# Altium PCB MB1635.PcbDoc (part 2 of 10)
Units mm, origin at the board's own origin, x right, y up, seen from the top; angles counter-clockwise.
Board outline 127 x 97 mm, 6 copper layers (Top Layer, Signal Layer 1, Signal Layer 2, Signal Layer 3, Signal Layer 4, Bottom Layer), stack 1.557 mm thick; 593 components, 478 nets, 2435 pads, 1743 vias.
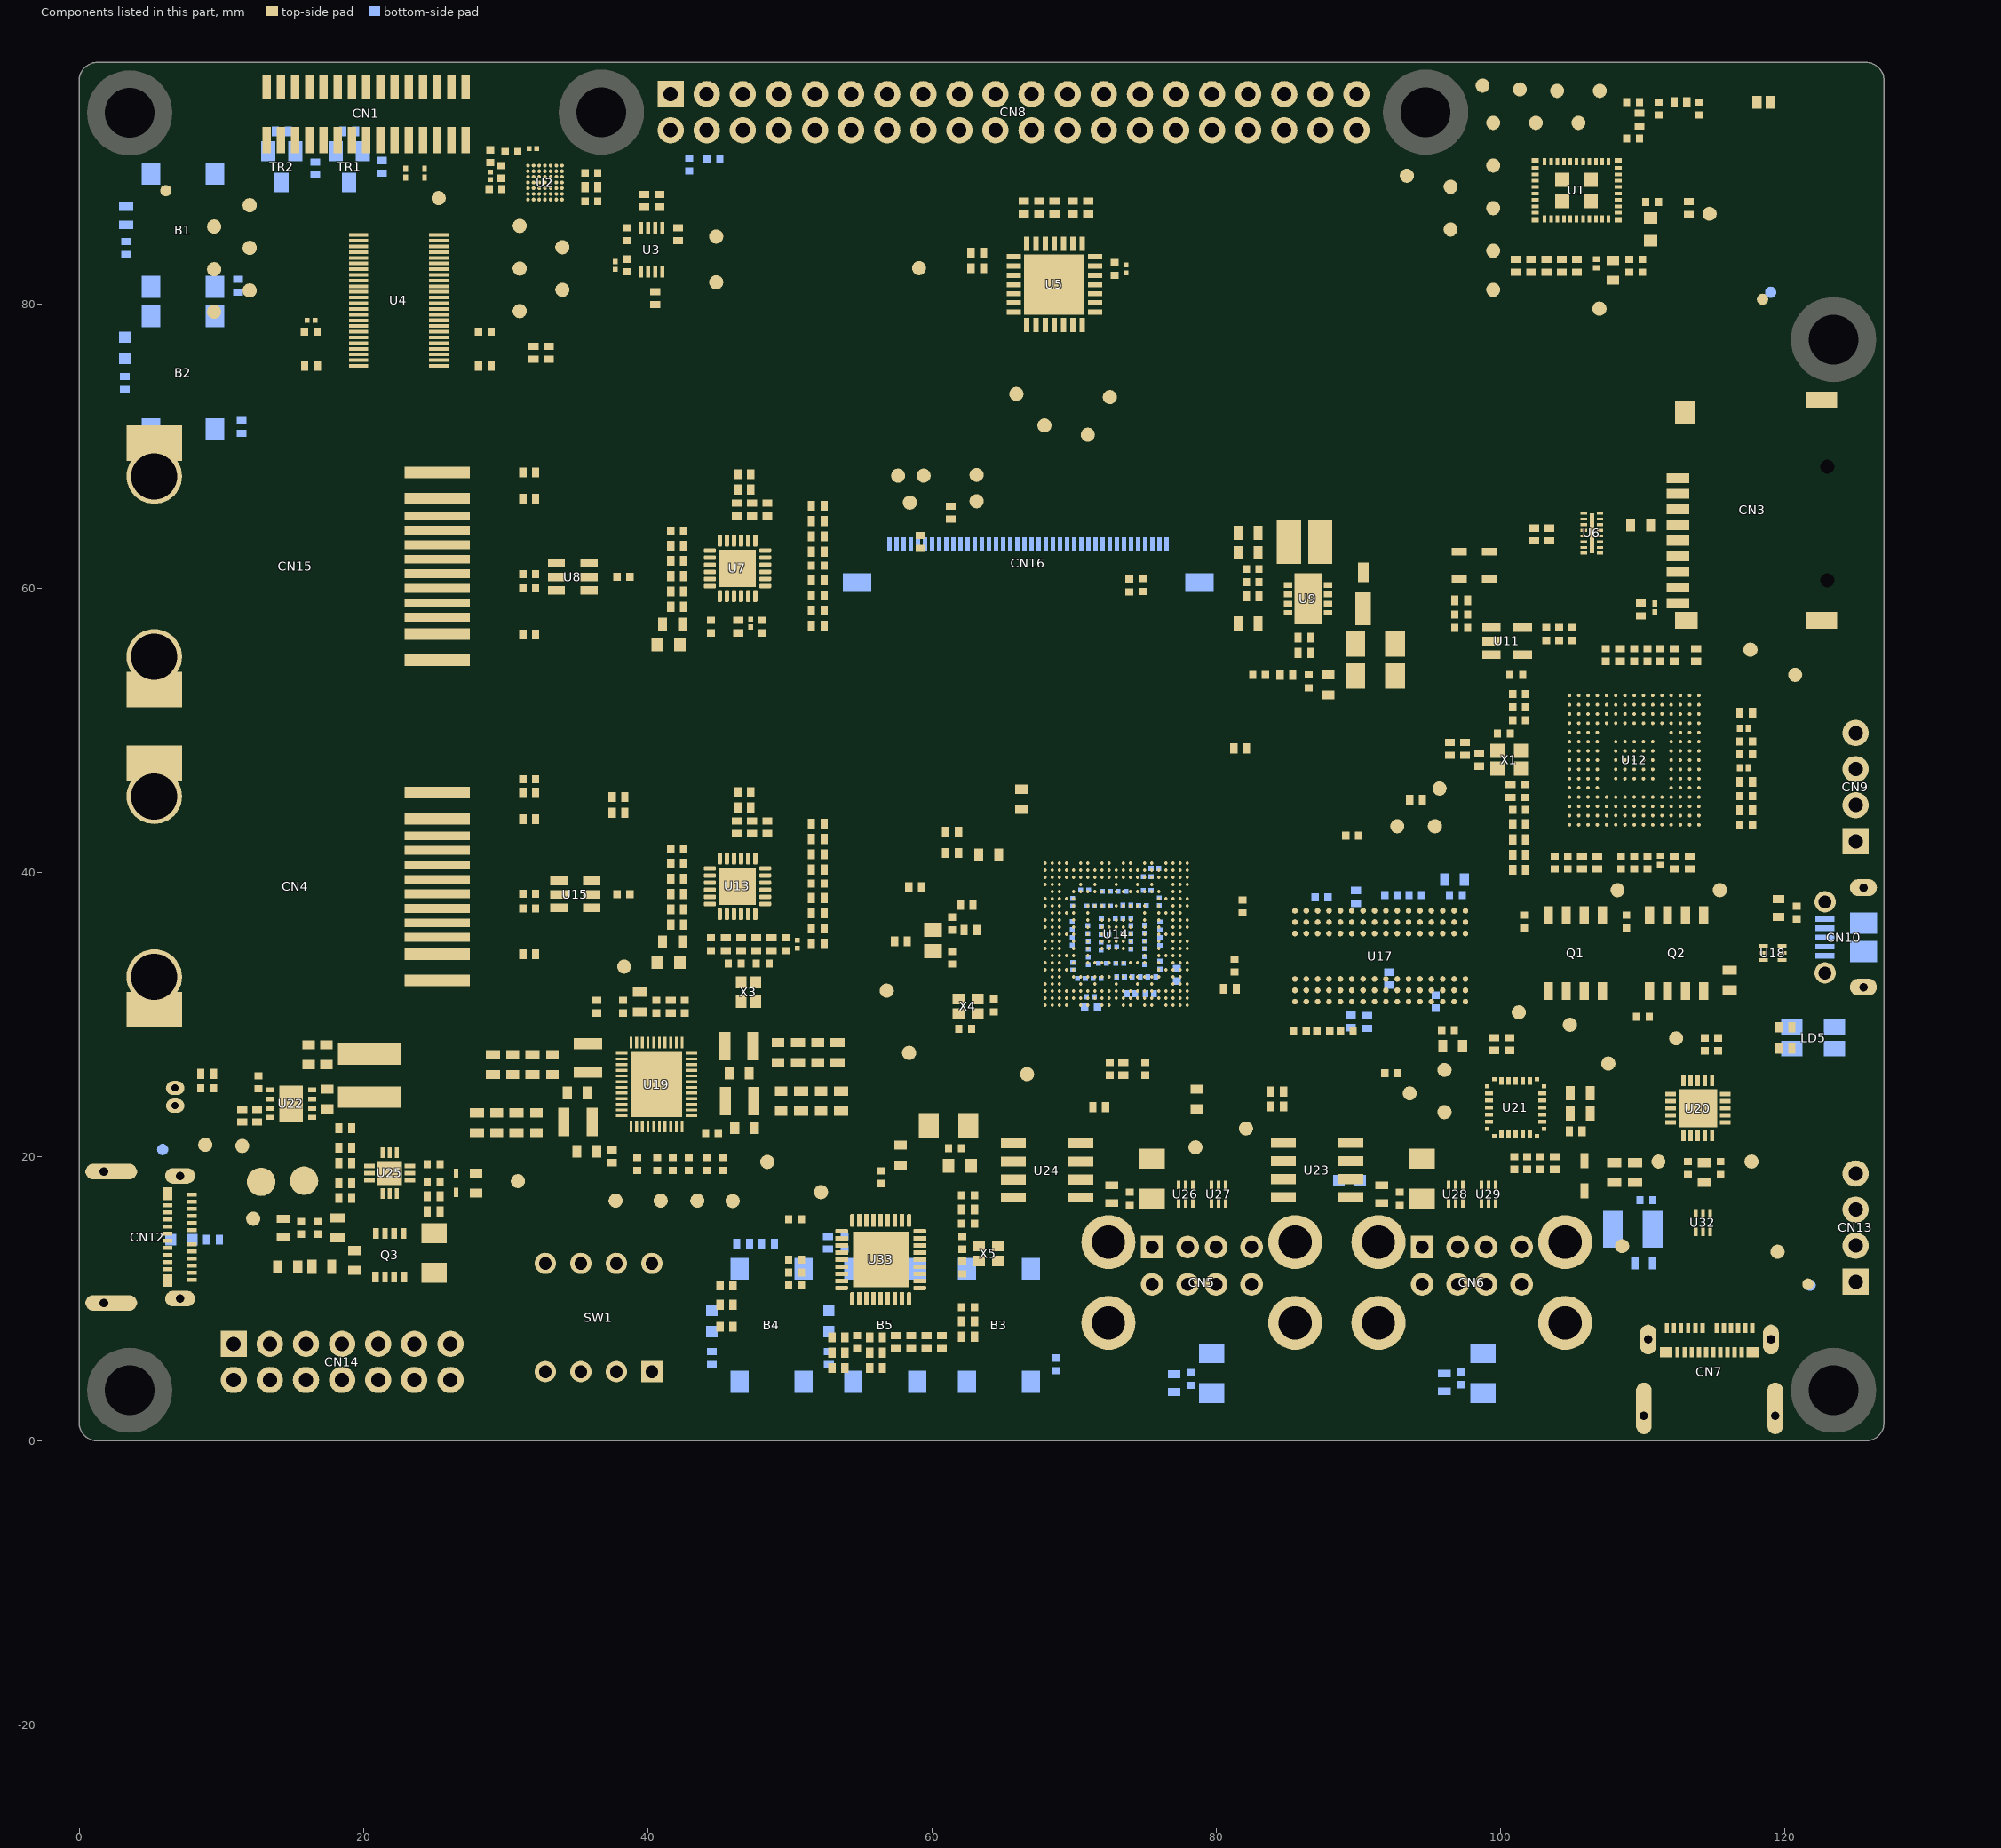
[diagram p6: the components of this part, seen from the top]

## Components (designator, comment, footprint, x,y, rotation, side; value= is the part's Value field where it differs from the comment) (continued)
U12 "ST-LINKV3E" ICC_UFBGA201_176+25_10X10_P065 109.425,47.9 r0 top value=ST-LINKV3S
U13 "LAN8742A-CZ-TR" ICC_VQFN24-EPAD_4X4_P050 46.325,39.025 r90 top
U14 "STM32MP135FAF7" ICC_TFBGA320_11X11_STM32MP135FA7_P050_H1P20 72.975,35.65 r0 top locked
U15 "USBLC6-4SC6" ESD_SOT23-6L 34.9,38.45 r270 top
U16 "ESD-TRANSIL" ESD_QFN2_1P6X1_P125 119.575,37.5 r90 top value=ESDA7P60-1U1M
U17 "NT5CC256M16ER-EK" ICC_VFBGA96_9x13_P080 91.55,34.1 r270 top locked
U18 "ECMF02-2AMX6" ESD_QFN-6L_1P7X1P5_P050 119.175,34.325 r270 top
U19 "STPMU1" ICC_WFQFN44-EPAD_5X6_P040 40.625,25.075 r0 top value=STPMIC1DPQR
U20 "TCPP03-M20" ICC_QFN20-EPAD_4X4_P050 113.9,23.4 r270 top
U21 "STM32G071G8U6N" ICC_UFQFPN28_4X4_P050 101.075,23.45 r0 top
U22 "ST1S31PUR" ICC_VFDFPN8-EPAD_3X3_P065 14.925,23.725 r270 top
U23 "STMPS2252MTR" ICC_SO8_5X4_P127 87.1,19.05 r270 top
U24 "STMPS2252MTR" ICC_SO8_5X4_P127 68.1,19.025 r270 top
U25 "TCPP01-M12" ICC_QFN12L-EPAD_3X3_P050 21.845,18.839 r270 top
U26 "ECMF02-2AMX6" ESD_QFN-6L_1P7X1P5_P050 77.85,17.35 r180 top
U27 "ECMF02-2AMX6" ESD_QFN-6L_1P7X1P5_P050 80.175,17.35 r180 top
U28 "ECMF02-2AMX6" ESD_QFN-6L_1P7X1P5_P050 96.85,17.35 r180 top
U29 "ECMF02-2AMX6" ESD_QFN-6L_1P7X1P5_P050 99.175,17.35 r180 top
U30 "ESD-TRANSIL" ESD_QFN1610_2N_1K_2A 72.65,17.35 r90 top value=ESDA7P120-1U1M
U31 "ESD-TRANSIL" ESD_QFN1610_2N_1K_2A 91.65,17.35 r90 top value=ESDA7P120-1U1M
U32 "ECMF02-2AMX6" ESD_QFN-6L_1P7X1P5_P050 114.25,15.35 r180 top
U33 "USB2514B-AEZC" ICC_QFN36-EPAD_6X6_P050 56.4,12.75 r180 top
U34 "ESD-TRANSIL" ESD_QFN1610_2N_1K_2A 14.345,14.989 r270 top value=ESDA25P35-1U1M
U35 "RK043FN78H-CT661C" LCD_DRAWING_ROCKTEK_RK043FN78H-CT661C 66.775,64.836 r180 bottom
U36 "ESD-TRANSIL" ESD_QFN1610_2N_1K_2A 110.1,12.523 r180 bottom value=ESDA25P35-1U1M
U37 "ESD-TRANSIL" ESD_ST0201 54.692,13.937 r90 bottom value=ESDALC6V1-1U2
U38 "ESD-TRANSIL" ESD_QFN1610_2N_1K_2A 96.075,4.1 r270 bottom value=ESDA7P120-1U1M
U39 "ESD-TRANSIL" ESD_QFN1610_2N_1K_2A 77.05,4.05 r270 bottom value=ESDA7P120-1U1M
U40 "ESD-TRANSIL" ESD_ST0201 24.3,89.213 r270 top value=ESDALC6V1-1U2
U41 "ESD-TRANSIL" ESD_ST0201 22.975,89.2 r270 top value=ESDALC6V1-1U2
X1 "OSCILLATOR_4_PINS" OSC_NDK_NZ2520SB_4P 100.625,47.925 r0 top value=25MHz
X2 "XTAL_2_PINS" CRY_NX2012SA_2P 60.075,35.2 r270 top value=32.768KHz
X3 "XTAL_4_PINS" CRY_NX2016SA_4P 47.1,31.575 r90 top value=25MHz
X4 "XTAL_4_PINS" CRY_NX2016SA_4P 62.55,30.575 r0 top value=24MHz
X5 "XTAL_4_PINS" CRY_NX2016SA_4P 63.975,13.175 r180 top value=24MHz

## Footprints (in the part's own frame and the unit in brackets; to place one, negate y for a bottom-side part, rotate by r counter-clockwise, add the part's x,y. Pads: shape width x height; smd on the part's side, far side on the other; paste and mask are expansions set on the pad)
C0201_H0P5 [mm] "MCD-01534"
  rect 0.4x0.5 smd mask+0.05: 1(-0.3,0) 2(0.3,0)
  Top Layer keep-out region: -0.099,-0.25 0.101,-0.25 0.101,0.25 -0.099,0.25
  body extent -0.35,-0.2 0.35,0.2, height 0.55
C0201_MURATA_GRM033_H0P3 [mm] "GRM033R60J105ME11"
  rect 0.35x0.35 smd mask+0.05: 1(-0.275,0) 2(0.275,0)
  Top Layer keep-out region: -0.1,-0.175 0.1,-0.175 0.1,0.175 -0.1,0.175
  body extent -0.32,-0.17 0.32,0.17, height 0.33
C0402#1 [mm]
  rect 0.51x0.56 smd mask+0.05: 1(-0.45,0) 2(0.45,0)
  Top Layer keep-out region: -0.175,-0.275 0.175,-0.275 0.175,0.275 -0.175,0.275
  body extent -0.5,-0.3 0.5,0.3, height 0.4
C0402#2 [mm]
  rect 0.51x0.56 smd mask+0.05: 1(-0.45,0) 2(0.45,0)
  body extent -0.5,-0.3 0.5,0.3, height 0.4
C0603 [mm]
  rect 0.64x0.89 smd mask+0.05: 1(-0.7,0) 2(0.7,0)
  Top Layer keep-out region: -0.375,-0.45 0.375,-0.45 0.375,0.45 -0.375,0.45
  body extent -0.9,-0.5 0.9,0.5, height 1.4
C0603_H0P8 [mm] "MCD-01540"
  rect 0.64x0.89 smd mask+0.05: 1(-0.7,0) 2(0.7,0)
  body extent -0.9,-0.5 0.9,0.5, height 1
C1206_H1P6 [mm]
  rect 1.4x1.78 smd mask+0.05: 1(-1.4,0) 2(1.4,0)
  silkscreen extent -2.12,-0.97 2.15,0.97, body extent -1.7,-0.9 1.7,0.9, height 1.8
C1206_H1P25 [mm]
  rect 1.4x1.78 smd mask+0.05: 1(-1.4,0) 2(1.4,0)
  silkscreen extent -2.12,-0.97 2.15,0.97, body extent -1.7,-0.9 1.7,0.9, height 1.45
C1210 [mm]
  rect 1.4x2.6 smd mask+0.05: 1(-1.4,0) 2(1.4,0)
  silkscreen extent -2.1,-1.43 2.1,1.43, body extent -1.75,-1.35 1.75,1.35, height 2.5
CON_DUAL-USB-TYPE-A_CONEXCON_5600-3081 [mm]
  round 1.6 hole 0.92: B1(-3.5,13.01) B2(-1,13.01) B3(1,13.01) B4(3.5,13.01) T2(-1,15.63) T3(1,15.63) T4(3.5,15.63)
  round 3.8 hole 2.33: CH1(6.57,10.3) CH2(-6.57,10.3) CH3(-6.57,15.98) CH4(6.57,15.98)
  rect 1.6x1.6 hole 0.92: T1(-3.5,15.63)
  silkscreen extent -7.3,-0.4 7.3,17.85, body extent -7.83,-0.6 7.87,17.85, height 16.2
CON_MICROSD_ATOM_MR01A-01211 [mm]
  rect 0.7x1.6 smd paste+0 mask+0.05: 1(2.25,14.5) 2(1.15,14.5) 3(0.05,14.5) 4(-1.05,14.5) 5(-2.15,14.5) 6(-3.25,14.5) 7(-4.35,14.5) 8(-5.45,14.5) 9(-6.55,14.5)
  rect 1.2x1.6 smd paste+0 mask+0.05: 10(-7.75,13.9)
  rect 1.2x2.2 smd paste+0 mask+0.05: 11(-7.75,4.4) 12(7.75,4.4)
  rect 1.6x1.4 smd paste+0 mask+0.05: 13(6.85,14)
  round 0.5 hole 1 unplated paste-10 mask+0.05: NPTH1(-4.95,4) NPTH2(3.05,4)
  Top Layer pour cut-out: -8.35,8.1 -8.35,12.9 -6.9,12.9 -6.9,8.1
  Top Layer pour cut-out: -6.1,10.1 2.9,10.1 2.9,8.1 -6.1,8.1
  Top Layer keep-out region: -8.35,8.1 -8.35,12.9 -6.9,12.9 -6.9,8.1
  Top Layer keep-out region: -6.1,10.1 2.9,10.1 2.9,8.1 -6.1,8.1
  silkscreen extent -7.35,-5.3 7.35,14.5, body extent -8.05,0 8.05,15, height 1.9
CON_MOLEX_53047-0210 [mm]
  oval 1x1.3 hole 0.5 mask+0.05: 1(-0.625,0) 2(0.625,0)
  silkscreen extent -2.12,-1.15 2.13,2.05, body extent -2.12,-1.15 2.13,2.05, height 4.2
CON_MOLEX_5051104091 [mm] "MCD-02589"
  rect 0.3x1 smd mask+0.05: 1(-9.75,1.1) 2(-9.25,1.1) 3(-8.75,1.1) 4(-8.25,1.1) 5(-7.75,1.1) 6(-7.25,1.1) 7(-6.75,1.1) 8(-6.25,1.1) 9(-5.75,1.1) 10(-5.25,1.1) 11(-4.75,1.1) 12(-4.25,1.1) 13(-3.75,1.1) 14(-3.25,1.1) 15(-2.75,1.1) 16(-2.25,1.1) 17(-1.75,1.1) 18(-1.25,1.1) 19(-0.75,1.1) 20(-0.25,1.1) 21(0.25,1.1) 22(0.75,1.1) 23(1.25,1.1) 24(1.75,1.1) 25(2.25,1.1) 26(2.75,1.1) 27(3.25,1.1) 28(3.75,1.1) 29(4.25,1.1) 30(4.75,1.1) 31(5.25,1.1) 32(5.75,1.1) 33(6.25,1.1) 34(6.75,1.1) 35(7.25,1.1) 36(7.75,1.1) 37(8.25,1.1) 38(8.75,1.1) 39(9.25,1.1) 40(9.75,1.1)
  rect 2x1.3 smd mask+0.05: MT1(-12.05,-1.6) MT2(12.05,-1.6)
  silkscreen extent -12.35,-4 12.35,1.25, body extent -12.75,-4 12.75,1.3, height 1.88
CON_RJ45_PHC_RMT-119A-12F6-GY-02 [mm] "MCD-02475"
  rect 0.81x4.6 smd mask+0.05: 1(6.61,25.2) 2(4.77,25.2) 11(-4.77,25.2) 12(-6.61,25.2)
  rect 0.61x4.6 smd mask+0.05: 3(3.57,25.2) 4(2.55,25.2) 5(1.53,25.2) 6(0.51,25.2) 7(-0.51,25.2) 8(-1.53,25.2) 9(-2.55,25.2) 10(-3.57,25.2)
  rect 2.5x3.9 smd mask+0.05: 13(-8.67,5.28) 14(8.67,5.28)
  round 3.9 hole 3.25 mask+0.05: 13(-6.35,5.28) 14(6.35,5.28)
  silkscreen extent -8.9,-0.01 8.9,25.65, body extent -9.5,0 9.5,25.65, height 13.61
CON_SAMTEC_TSW-104-07-G-S [mm]
  rect 1.85x1.85 / inner round 1.85 / far side rect 1.85x1.85 hole 1 mask+0.05: 1(-3.81,0)
  round 1.85 hole 1 mask+0.05: 2(-1.27,0) 3(1.27,0) 4(3.81,0)
  silkscreen extent -5.12,-1.3 5.12,1.3, body extent -5.21,-1.37 5.18,1.37, height 8.38
CON_SAMTEC_TSW-107-07-X-D [mm] "MCD-02123"
  rect 1.85x1.85 / inner round 1.85 / far side rect 1.85x1.85 hole 1 mask+0.05: 1(-7.62,-1.27)
  round 1.85 hole 1 mask+0.05: 2(-7.62,1.27) 3(-5.08,-1.27) 4(-5.08,1.27) 5(-2.54,-1.27) 6(-2.54,1.27) 7(0,-1.27) 8(0,1.27) 9(2.54,-1.27) 10(2.54,1.27) 11(5.08,-1.27) 12(5.08,1.27) 13(7.62,-1.27) 14(7.62,1.27)
  silkscreen extent -8.89,-2.54 8.89,2.54, body extent -8.89,-2.55 8.89,2.54, height 8.38
CON_SAMTEC_TSW-120-07-G-D [mm]
  rect 1.85x1.85 / inner round 1.85 / far side rect 1.85x1.85 hole 1 mask+0.05: 1(-24.13,-1.27)
  round 1.85 hole 1 mask+0.05: 2(-24.13,1.27) 3(-21.59,-1.27) 4(-21.59,1.27) 5(-19.05,-1.27) 6(-19.05,1.27) 7(-16.51,-1.27) 8(-16.51,1.27) 9(-13.97,-1.27) 10(-13.97,1.27) 11(-11.43,-1.27) 12(-11.43,1.27) 13(-8.89,-1.27) 14(-8.89,1.27) 15(-6.35,-1.27) 16(-6.35,1.27) 17(-3.81,-1.27) 18(-3.81,1.27) 19(-1.27,-1.27) 20(-1.27,1.27) 21(1.27,-1.27) 22(1.27,1.27) 23(3.81,-1.27) 24(3.81,1.27) 25(6.35,-1.27) 26(6.35,1.27) 27(8.89,-1.27) 28(8.89,1.27) 29(11.43,-1.27) 30(11.43,1.27) 31(13.97,-1.27) 32(13.97,1.27) 33(16.51,-1.27) 34(16.51,1.27) 35(19.05,-1.27) 36(19.05,1.27) 37(21.59,-1.27) 38(21.59,1.27) 39(24.13,-1.27) 40(24.13,1.27)
  silkscreen extent -25.4,-2.54 25.4,2.54, body extent -25.4,-2.55 25.4,2.54, height 8.38
CON_TE-CONNECTIVITY_1-1734248-5 [mm] "MCD-02225"
  rect 0.6x1.85 smd mask+0.05: 1(7,1.875) 2(6,1.875) 3(5,1.875) 4(4,1.875) 5(3,1.875) 6(2,1.875) 7(1,1.875) 8(0,1.875) 9(-1,1.875) 10(-2,1.875) 11(-3,1.875) 12(-4,1.875) 13(-5,1.875) 14(-6,1.875) 15(-7,1.875)
  rect 0.6x1.65 smd mask+0.05: 16(7,-1.875) 17(6,-1.875) 18(5,-1.875) 19(4,-1.875) 20(3,-1.875) 21(2,-1.875) 22(1,-1.875) 23(0,-1.875) 24(-1,-1.875) 25(-2,-1.875) 26(-3,-1.875) 27(-4,-1.875) 28(-5,-1.875) 29(-6,-1.875) 30(-7,-1.875)
  silkscreen extent -11.2,-2.85 11.2,1.85, body extent -11.2,-2.7 11.2,2.4, height 7.7
CON_USB-TYPEC_MOLEX_2012670005 [mm] "MCD-02421"
  rect 0.3x0.7 smd mask+0.05: A1(-3,3.085) A2(-2.5,3.085) A3(-2,3.085) A4(-1.5,3.085) A5(-1,3.085) A6(-0.5,3.085) A7(0.5,3.085) A8(1,3.085) A9(1.5,3.085) A10(2,3.085) A11(2.5,3.085) A12(3,3.085) B2(2.25,1.385) B3(1.75,1.385) B4(1.25,1.385) B5(0.75,1.385) B6(0.25,1.385) B7(-0.25,1.385) B8(-0.75,1.385) B9(-1.25,1.385) B10(-1.75,1.385) B11(-2.25,1.385)
  rect 0.9x0.7 smd mask+0.05: B1(3.05,1.385) B12(-3.05,1.385)
  oval 1.1x2.1 hole 0.6 slot 1.6 at 90 deg mask+0.05: SH1(-4.32,2.275) SH2(4.32,2.275)
  oval 1.1x2.6 hole 0.6 slot 2.1 at 90 deg mask+0.05: SH3(-4.62,-3.085) SH4(4.62,-3.085)
  oval 1.1x3.6 all layers, no hole mask+0.05: SH3(-4.62,-2.55) SH4(4.62,-2.55)
  silkscreen extent -4.7,-5.02 4.7,1.1, body extent -4.7,-5.03 4.69,3.27, height 3.67
CON_USBMICROB_MOLEX_105017-0001_H2P90 [mm]
  rect 0.4x1.35 smd mask+0.05: 1(-1.3,4.15) 2(-0.65,4.15) 3(0,4.15) 4(0.65,4.15) 5(1.3,4.15)
  round 1.5 hole 0.9 mask+0.05: 6(-2.5,4.15) 7(2.5,4.15)
  oval 1.2x1.9 hole 0.6 slot 1.3 at 90 deg mask+0.05: 8(3.5,1.45) 9(-3.5,1.45)
  rect 1.5x1.9 smd mask+0.05: 10(-1,1.45) 11(1,1.45)
  Top Layer region: 2.3,2.4 3.5,2.4 3.5,0.5 2.3,0.5 2.3,2.4
  Top Layer region: -3.5,2.4 -2.3,2.4 -2.3,0.5 -3.5,0.5 -3.5,2.4
  silkscreen extent -4,-0.7 4,4.6, body extent -4.1,-1.15 4.1,4.66, height 2.9
CRY_NX2012SA_2P [mm]
  rect 1x1.25 smd mask+0.05: 1(-0.75,0) 2(0.75,0)
  silkscreen extent -1.05,-0.75 1.05,0.75, body extent -1.05,-0.63 1.05,0.63, height 0.6
CRY_NX2016SA_4P [mm]
  rect 0.85x0.75 smd mask+0.05: 1(-0.675,-0.525) 2(0.675,-0.525) 3(0.675,0.525) 4(-0.675,0.525)
  silkscreen extent -1.22,-1.02 1.05,0.85, body extent -1.05,-0.85 1.05,0.85, height 0.7
DIO_DO216-AA [mm]
  rect 1.38x0.75 smd mask+0.05: 1(1.515,0)
  rect 2.32x1.1 smd mask+0.05: 2(-1.045,0)
  Top Layer region: -1.705,-1.015 0.115,-1.015 0.115,1.015 -1.705,1.015
  silkscreen extent -2.25,-1.22 0.72,1.22, body extent -2.02,-1.02 1.83,1.02, height 1.15
DIO_SOD323 [mm]
  rect 1.06x0.54 smd mask+0.05: 1(-1.07,0) 2(1.07,0)
  silkscreen extent -0.9,-0.72 0.9,0.72, body extent -1.3,-0.78 1.3,0.78, height 1.17
DIO_SOD523_1A_2K [mm] "MCD-01677"
  rect 0.65x0.3 smd mask+0.05: 1(-0.675,0) 2(0.675,0)
  silkscreen extent -0.65,-0.45 1.05,0.55, body extent -0.85,-0.45 0.85,0.45, height 0.71
ESD_QFN2_1P6X1_P125 [mm]
  rect 0.55x0.8 smd mask+0.05: 1(-0.625,0) 2(0.625,0)
  silkscreen extent -1,-0.55 0.85,0.55, body extent -0.85,-0.55 0.85,0.55, height 0.61
ESD_QFN1610_2N_1K_2A [mm] "DFN, 2-Leads, Body 1.60x1.00mm"
  rect 0.55x0.9 smd mask+0.05: 1(-0.625,0) 2(0.625,0)
  silkscreen extent -1.02,-0.58 0.85,0.58, body extent -0.85,-0.55 0.85,0.55, height 0.6
ESD_QFN-6L_1P7X1P5_P050 [mm]
  rect 0.25x0.6 smd mask+0.05: 1(-0.5,-0.65) 2(0,-0.65) 3(0.5,-0.65) 4(0.5,0.65) 5(0,0.65) 6(-0.5,0.65)
  body extent -0.9,-0.8 0.9,0.8, height 0.56
ESD_SOT23-6L [mm]
  rect 0.6x1.2 smd mask+0.05: 1(-0.95,-1.15) 2(0,-1.15) 3(0.95,-1.15) 4(0.95,1.15) 5(0,1.15) 6(-0.95,1.15)
  silkscreen extent -1.53,-0.87 1.53,0.87, body extent -1.52,-1.5 1.52,1.5, height 1.45
ESD_ST0201 [mm]
  rect 0.425x0.33 smd mask+0.05: 1(-0.312,0) 2(0.312,0)
  silkscreen extent -0.55,-0.3 0.33,0.3, body extent -0.34,-0.18 0.34,0.18, height 0.34
ESD_UQFN16L-EPAD_3P5X1P2_P040 [mm]
  rect 0.2x0.45 smd mask+0.05: 1(-1.4,-0.575) 2(-1,-0.575) 3(-0.6,-0.575) 4(-0.2,-0.575) 5(0.2,-0.575) 6(0.6,-0.575) 7(1,-0.575) 8(1.4,-0.575) 9(1.4,0.575) 10(1,0.575) 11(0.6,0.575) 12(0.2,0.575) 13(-0.2,0.575) 14(-0.6,0.575) 15(-1,0.575) 16(-1.4,0.575)
  rect 2.8x0.3 smd mask+0.05: EP(0,0)
  body extent -1.78,-0.63 1.78,0.63, height 0.56
FIL_0603_H0P65 [mm]
  rect 0.8x0.95 smd mask+0.05: 1(-0.8,0) 2(0.8,0)
  silkscreen extent -1.33,-0.6 1.33,0.6, body extent -0.87,-0.47 0.87,0.47, height 0.65
ICC_QFN8-EPAD_3X3_P065 [mm]
  rect 0.4x0.6 smd paste+0 mask+0.05: 1(-0.975,-1.4) 2(-0.325,-1.4) 3(0.325,-1.4) 4(0.975,-1.4) 5(0.975,1.4) 6(0.325,1.4) 7(-0.325,1.4) 8(-0.975,1.4)
  rect 3.6x1.9 smd paste+0 mask+0: 9(0,0)
  body extent -1.58,-1.58 1.58,1.58, height 1
ICC_QFN12L-EPAD_3X3_P050 [mm] "MCD-01809"
  rect 0.3x0.75 smd mask+0.05: 1(-0.5,-1.425) 2(0,-1.425) 3(0.5,-1.425) 7(0.5,1.425) 8(0,1.425) 9(-0.5,1.425)
  rect 0.75x0.3 smd mask+0.05: 4(1.425,-0.5) 5(1.425,0) 6(1.425,0.5) 10(-1.425,0.5) 11(-1.425,0) 12(-1.425,-0.5)
  rect 1.7x1.7 smd mask+0.05: 13(0,0)
  body extent -1.55,-1.55 1.55,1.55, height 0.8
ICC_QFN20-EPAD_4X4_P050 [mm] "MCD-02130"
  rect 0.75x0.3 smd mask+0.05: 1(-1.925,1) 2(-1.925,0.5) 3(-1.925,0) 4(-1.925,-0.5) 5(-1.925,-1) 11(1.925,-1) 12(1.925,-0.5) 13(1.925,0) 14(1.925,0.5) 15(1.925,1)
  rect 0.3x0.75 smd mask+0.05: 6(-1,-1.925) 7(-0.5,-1.925) 8(0,-1.925) 9(0.5,-1.925) 10(1,-1.925) 16(1,1.925) 17(0.5,1.925) 18(0,1.925) 19(-0.5,1.925) 20(-1,1.925)
  rect 2.7x2.7 smd mask+0.05: 21(0,0)
  body extent -2.13,-2.13 2.13,2.13, height 1.01
ICC_QFN28-EPAD_6X6_P065 [mm] "MCD-02210"
  rect 0.37x1 smd mask+0.05: 1(-1.95,-2.85) 2(-1.3,-2.85) 3(-0.65,-2.85) 4(0,-2.85) 5(0.65,-2.85) 6(1.3,-2.85) 7(1.95,-2.85) 15(1.95,2.85) 16(1.3,2.85) 17(0.65,2.85) 18(0,2.85) 19(-0.65,2.85) 20(-1.3,2.85) 21(-1.95,2.85)
  rect 1x0.37 smd mask+0.05: 8(2.85,-1.95) 9(2.85,-1.3) 10(2.85,-0.65) 11(2.85,0) 12(2.85,0.65) 13(2.85,1.3) 14(2.85,1.95) 22(-2.85,1.95) 23(-2.85,1.3) 24(-2.85,0.65) 25(-2.85,0) 26(-2.85,-0.65) 27(-2.85,-1.3) 28(-2.85,-1.95)
  rect 4.25x4.25 smd mask+0.05: 29(0,0)
  body extent -3.05,-3.05 3.05,3.05, height 1
ICC_QFN36-EPAD_6X6_P050 [mm]
  rrect50% 0.3x0.9 smd mask+0.05: 1(-2,-2.75) 9(2,-2.75) 19(2,2.75) 27(-2,2.75)
  rect 0.3x0.9 smd mask+0.05: 2(-1.5,-2.75) 3(-1,-2.75) 4(-0.5,-2.75) 5(0,-2.75) 6(0.5,-2.75) 7(1,-2.75) 8(1.5,-2.75) 20(1.5,2.75) 21(1,2.75) 22(0.5,2.75) 23(0,2.75) 24(-0.5,2.75) 25(-1,2.75) 26(-1.5,2.75)
  rrect50% 0.9x0.3 smd mask+0.05: 10(2.75,-2) 18(2.75,2) 28(-2.75,2) 36(-2.75,-2)
  rect 0.9x0.3 smd mask+0.05: 11(2.75,-1.5) 12(2.75,-1) 13(2.75,-0.5) 14(2.75,0) 15(2.75,0.5) 16(2.75,1) 17(2.75,1.5) 29(-2.75,1.5) 30(-2.75,1) 31(-2.75,0.5) 32(-2.75,0) 33(-2.75,-0.5) 34(-2.75,-1) 35(-2.75,-1.5)
  rect 3.9x3.9 smd mask+0.05: 37(0,0)
  body extent -3.06,-3.06 3.06,3.06, height 1
ICC_SO8_5X4_P127 [mm]
  rect 0.7x1.75 smd mask+0.05: 1(-1.905,-2.375) 2(-0.635,-2.375) 3(0.635,-2.375) 4(1.905,-2.375) 5(1.905,2.375) 6(0.635,2.375) 7(-0.635,2.375) 8(-1.905,2.375)
  silkscreen extent -2.73,-3.25 2.58,2, body extent -2.57,-3 2.57,3, height 1.75
ICC_TFBGA320_11X11_STM32MP135FA7_P050_H1P20 [mm] "MCD-02251"
  round 0.23 smd paste+0.025 mask+0.05: A1(-5,5) A2(-4.5,5) A3(-4,5) A4(-3.5,5) A6(-2.5,5) A7(-2,5) A9(-1,5) A10(-0.5,5) A12(0.5,5) A13(1,5) A15(2,5) A16(2.5,5) A18(3.5,5) A19(4,5) A20(4.5,5) A21(5,5) AA1(-5,-5) AA2(-4.5,-5) AA3(-4,-5) AA4(-3.5,-5) AA6(-2.5,-5) AA7(-2,-5) AA9(-1,-5) AA10(-0.5,-5) AA12(0.5,-5) AA13(1,-5) AA15(1.999,-5) AA16(2.499,-5) AA18(3.499,-5) AA19(3.999,-5) AA20(4.499,-5) AA21(4.999,-5) B1(-5,4.5) B2(-4.5,4.5) B3(-4,4.5) B4(-3.5,4.5) B5(-3,4.5) B6(-2.5,4.5) B7(-2,4.5) B8(-1.5,4.5) B9(-1,4.5) B10(-0.5,4.5) B11(0,4.5) B12(0.5,4.5) B13(1,4.5) B14(1.5,4.5) B15(2,4.5) B16(2.5,4.5) B17(3,4.5) B18(3.5,4.5) B19(4,4.5) B20(4.5,4.5) B21(5,4.5) C1(-5,4) C2(-4.5,4) C3(-4,4) C4(-3.5,4) C5(-3,4) C6(-2.5,4) C7(-2,4) C8(-1.5,4) C9(-1,4) C10(-0.5,4) C11(0,4) C12(0.5,4) C13(1,4) C14(1.5,4) C15(2,4) C16(2.5,4) C17(3,4) C18(3.5,4) C19(4,4) C20(4.5,4) C21(5,4) D1(-5,3.5) D2(-4.5,3.5) D3(-4,3.5) D6(-2.5,3.5) D8(-1.5,3.5) D11(0,3.5) D14(1.5,3.5) D16(2.5,3.5) D19(4,3.5) D20(4.5,3.5) D21(5,3.5) E2(-4.5,3) E3(-4,3) E5(-3,3) E6(-2.5,3) E7(-2,3) E8(-1.5,3) E9(-1,3) E10(-0.5,3) E11(0,3) E12(0.5,3) E13(1,3) E14(1.5,3) E15(2,3) E16(2.5,3) E17(3,3) E19(4,3) E20(4.5,3) F1(-5,2.5) F2(-4.5,2.5) F3(-4,2.5) F4(-3.5,2.5) F5(-3,2.5) F17(3,2.5) F18(3.5,2.5) F19(4,2.5) F20(4.5,2.5) F21(5,2.5) G1(-5,2) G2(-4.5,2) G3(-4,2) G5(-3,2) G7(-2,2) G8(-1.5,2) G9(-1,2) G10(-0.5,2) G11(0,2) G12(0.5,2) G13(1,2) G14(1.5,2) G15(2,2) G17(3,2) G19(4,2) G20(4.5,2) G21(5,2) H2(-4.5,1.5) H3(-4,1.5) H4(-3.5,1.5) H5(-3,1.5) H7(-2,1.5) H15(2,1.5) H17(3,1.5) H18(3.5,1.5) H19(4,1.5) H20(4.5,1.5) J1(-5,1) J2(-4.5,1) J3(-4,1) J5(-3,1) J7(-2,1) J9(-1,1) J10(-0.5,1) J11(0,1) J12(0.5,1) J13(1,1) J15(1.999,1) J17(2.999,1) J19(3.999,1) J20(4.499,1) J21(4.999,1) K1(-5,0.5) K2(-4.5,0.5) K3(-4,0.5) K5(-3,0.5) K7(-2,0.5) K9(-1,0.5) K10(-0.5,0.5) K11(0,0.5) K12(0.5,0.5) K13(1,0.5) K15(2,0.5) K17(2.999,0.5) K19(3.999,0.5) K20(4.499,0.5) K21(4.999,0.5) L2(-4.5,0) L3(-4,0) L4(-3.5,0) L5(-3,0) L7(-2,0) L9(-1,0) L10(-0.5,0) L12(0.5,0) L13(1,0) L15(2,0) L17(2.999,0) L18(3.499,0) L19(3.999,0) L20(4.499,0) M1(-5,-0.5) M2(-4.5,-0.5) M3(-4,-0.5) M5(-3,-0.5) M7(-2,-0.5) M9(-1,-0.5) M10(-0.5,-0.5) M11(0,-0.5) M12(0.5,-0.5) M13(1,-0.5) M15(2,-0.5) M17(3,-0.5) M19(4,-0.5) M20(4.5,-0.5) M21(5,-0.5) N1(-5,-1) N2(-4.5,-1) N3(-4,-1) N5(-3,-1) N7(-2,-1) N9(-1,-1) N10(-0.5,-1) N11(0,-1) N12(0.5,-1) N13(1,-1) N15(2,-1) N17(3,-1) N19(4,-1) N20(4.5,-1) N21(5,-1) P2(-4.5,-1.5) P3(-4,-1.5) P4(-3.5,-1.5) P5(-3,-1.5) P7(-2,-1.5) P15(2,-1.5) P17(3,-1.5) P18(3.5,-1.5) P19(4,-1.5) P20(4.5,-1.5) R1(-5,-2) R2(-4.5,-2) R3(-4,-2) R5(-3,-2) R7(-2,-2) R8(-1.5,-2) R9(-1,-2) R10(-0.5,-2) R11(0,-2) R12(0.5,-2) R13(1,-2) R14(1.5,-2) R15(2,-2) R17(2.999,-2) R19(3.999,-2) R20(4.499,-2) R21(4.999,-2) T1(-5,-2.5) T2(-4.5,-2.5) T3(-4,-2.5) T4(-3.5,-2.5) T5(-3,-2.5) T17(2.999,-2.5) T18(3.499,-2.5) T19(3.999,-2.5) T20(4.499,-2.5) T21(4.999,-2.5) U2(-4.5,-3) U3(-4,-3) U5(-3,-3) U6(-2.5,-3) U7(-2,-3) U8(-1.5,-3) U9(-1,-3) U10(-0.5,-3) U11(0,-3) U12(0.5,-3) U13(1,-3) U14(1.5,-3) U15(1.999,-3) U16(2.499,-3) U17(2.999,-3) U19(3.999,-3) U20(4.499,-3) V1(-5,-3.5) V2(-4.5,-3.5) V3(-4,-3.5) V6(-2.5,-3.5) V8(-1.5,-3.5) V11(-0.001,-3.5) V14(1.499,-3.5) V16(2.499,-3.5) V19(3.999,-3.5) V20(4.499,-3.5) V21(4.999,-3.5) W1(-5,-4) W2(-4.5,-4) W3(-4,-4) W4(-3.5,-4) W5(-3,-4) W6(-2.5,-4) W7(-2,-4) W8(-1.5,-4) W9(-1,-4) W10(-0.5,-4) W11(0,-4) W12(0.5,-4) W13(1,-4) W14(1.5,-4) W15(1.999,-4) W16(2.499,-4) W17(2.999,-4) W18(3.499,-4) W19(3.999,-4) W20(4.499,-4) W21(4.999,-4) Y1(-5,-4.5) Y2(-4.5,-4.5) Y3(-4,-4.5) Y4(-3.5,-4.5) Y5(-3,-4.5) Y6(-2.5,-4.5) Y7(-2,-4.5) Y8(-1.5,-4.5) Y9(-1,-4.5) Y10(-0.5,-4.5) Y11(0,-4.5) Y12(0.5,-4.5) Y13(1,-4.5) Y14(1.5,-4.5) Y15(1.999,-4.5) Y16(2.499,-4.5) Y17(2.999,-4.5) Y18(3.499,-4.5) Y19(3.999,-4.5) Y20(4.499,-4.5) Y21(4.999,-4.5)
  silkscreen extent -5.8,-5.5 5.5,5.8, body extent -5.5,-5.52 5.5,5.52, height 1.11
ICC_TVSOP48_9P8X6P6_P040 [mm] "MCD-02226"
  rect 0.25x1.35 smd mask+0.038: 1(-4.6,-2.825) 2(-4.2,-2.825) 3(-3.8,-2.825) 4(-3.4,-2.825) 5(-3,-2.825) 6(-2.6,-2.825) 7(-2.2,-2.825) 8(-1.8,-2.825) 9(-1.4,-2.825) 10(-1,-2.825) 11(-0.6,-2.825) 12(-0.2,-2.825) 13(0.2,-2.825) 14(0.6,-2.825) 15(1,-2.825) 16(1.4,-2.825) 17(1.8,-2.825) 18(2.2,-2.825) 19(2.6,-2.825) 20(3,-2.825) 21(3.4,-2.825) 22(3.8,-2.825) 23(4.2,-2.825) 24(4.6,-2.825) 25(4.6,2.825) 26(4.2,2.825) 27(3.8,2.825) 28(3.4,2.825) 29(3,2.825) 30(2.6,2.825) 31(2.2,2.825) 32(1.8,2.825) 33(1.4,2.825) 34(1,2.825) 35(0.6,2.825) 36(0.2,2.825) 37(-0.2,2.825) 38(-0.6,2.825) 39(-1,2.825) 40(-1.4,2.825) 41(-1.8,2.825) 42(-2.2,2.825) 43(-2.6,2.825) 44(-3,2.825) 45(-3.4,2.825) 46(-3.8,2.825) 47(-4.2,2.825) 48(-4.6,2.825)
  silkscreen extent -4.9,-1.9 4.9,1.9, body extent -4.9,-3.2 4.9,3.2, height 1.2
ICC_UFBGA201_176+25_10X10_P065 [mm] "IPC"
  round 0.25 smd mask+0.05: A1(-4.55,4.55) A2(-3.9,4.55) A3(-3.25,4.55) A4(-2.6,4.55) A5(-1.95,4.55) A6(-1.3,4.55) A7(-0.65,4.55) A8(0,4.55) A9(0.65,4.55) A10(1.3,4.55) A11(1.95,4.55) A12(2.6,4.55) A13(3.25,4.55) A14(3.9,4.55) A15(4.55,4.55) B1(-4.55,3.9) B2(-3.9,3.9) B3(-3.25,3.9) B4(-2.6,3.9) B5(-1.95,3.9) B6(-1.3,3.9) B7(-0.65,3.9) B8(0,3.9) B9(0.65,3.9) B10(1.3,3.9) B11(1.95,3.9) B12(2.6,3.9) B13(3.25,3.9) B14(3.9,3.9) B15(4.55,3.9) C1(-4.55,3.25) C2(-3.9,3.25) C3(-3.25,3.25) C4(-2.6,3.25) C5(-1.95,3.25) C6(-1.3,3.25) C7(-0.65,3.25) C8(0,3.25) C9(0.65,3.25) C10(1.3,3.25) C11(1.95,3.25) C12(2.6,3.25) C13(3.25,3.25) C14(3.9,3.25) C15(4.55,3.25) D1(-4.55,2.6) D2(-3.9,2.6) D3(-3.25,2.6) D4(-2.6,2.6) D5(-1.95,2.6) D6(-1.3,2.6) D7(-0.65,2.6) D8(0,2.6) D9(0.65,2.6) D10(1.3,2.6) D11(1.95,2.6) D12(2.6,2.6) D13(3.25,2.6) D14(3.9,2.6) D15(4.55,2.6) E1(-4.55,1.95) E2(-3.9,1.95) E3(-3.25,1.95) E4(-2.6,1.95) E12(2.6,1.95) E13(3.25,1.95) E14(3.9,1.95) E15(4.55,1.95) F1(-4.55,1.3) F2(-3.9,1.3) F3(-3.25,1.3) F4(-2.6,1.3) F6(-1.3,1.3) F7(-0.65,1.3) F8(0,1.3) F9(0.65,1.3) F10(1.3,1.3) F12(2.6,1.3) F13(3.25,1.3) F14(3.9,1.3) F15(4.55,1.3) G1(-4.55,0.65) G2(-3.9,0.65) G3(-3.25,0.65) G4(-2.6,0.65) G6(-1.3,0.65) G7(-0.65,0.65) G8(0,0.65) G9(0.65,0.65) G10(1.3,0.65) G12(2.6,0.65) G13(3.25,0.65) G14(3.9,0.65) G15(4.55,0.65) H1(-4.55,0) H2(-3.9,0) H3(-3.25,0) H4(-2.6,0) H6(-1.3,0) H7(-0.65,0) H8(0,0) H9(0.65,0) H10(1.3,0) H12(2.6,0) H13(3.25,0) H14(3.9,0) H15(4.55,0) J1(-4.55,-0.65) J2(-3.9,-0.65) J3(-3.25,-0.65) J4(-2.6,-0.65) J6(-1.3,-0.65) J7(-0.65,-0.65) J8(0,-0.65) J9(0.65,-0.65) J10(1.3,-0.65) J12(2.6,-0.65) J13(3.25,-0.65) J14(3.9,-0.65) J15(4.55,-0.65) K1(-4.55,-1.3) K2(-3.9,-1.3) K3(-3.25,-1.3) K4(-2.6,-1.3) K6(-1.3,-1.3) K7(-0.65,-1.3) K8(0,-1.3) K9(0.65,-1.3) K10(1.3,-1.3) K12(2.6,-1.3) K13(3.25,-1.3) K14(3.9,-1.3) K15(4.55,-1.3) L1(-4.55,-1.95) L2(-3.9,-1.95) L3(-3.25,-1.95) L4(-2.6,-1.95) L12(2.6,-1.95) L13(3.25,-1.95) L14(3.9,-1.95) L15(4.55,-1.95) M1(-4.55,-2.6) M2(-3.9,-2.6) M3(-3.25,-2.6) M4(-2.6,-2.6) M5(-1.95,-2.6) M6(-1.3,-2.6) M7(-0.65,-2.6) M8(0,-2.6) M9(0.65,-2.6) M10(1.3,-2.6) M11(1.95,-2.6) M12(2.6,-2.6) M13(3.25,-2.6) M14(3.9,-2.6) M15(4.55,-2.6) N1(-4.55,-3.25) N2(-3.9,-3.25) N3(-3.25,-3.25) N4(-2.6,-3.25) N5(-1.95,-3.25) N6(-1.3,-3.25) N7(-0.65,-3.25) N8(0,-3.25) N9(0.65,-3.25) N10(1.3,-3.25) N11(1.95,-3.25) N12(2.6,-3.25) N13(3.25,-3.25) N14(3.9,-3.25) N15(4.55,-3.25) P1(-4.55,-3.9) P2(-3.9,-3.9) P3(-3.25,-3.9) P4(-2.6,-3.9) P5(-1.95,-3.9) P6(-1.3,-3.9) P7(-0.65,-3.9) P8(0,-3.9) P9(0.65,-3.9) P10(1.3,-3.9) P11(1.95,-3.9) P12(2.6,-3.9) P13(3.25,-3.9) P14(3.9,-3.9) P15(4.55,-3.9) R1(-4.55,-4.55) R2(-3.9,-4.55) R3(-3.25,-4.55) R4(-2.6,-4.55) R5(-1.95,-4.55) R6(-1.3,-4.55) R7(-0.65,-4.55) R8(0,-4.55) R9(0.65,-4.55) R10(1.3,-4.55) R11(1.95,-4.55) R12(2.6,-4.55) R13(3.25,-4.55) R14(3.9,-4.55) R15(4.55,-4.55)
  silkscreen extent -5.22,-5.07 5.07,5.23, body extent -5.07,-5.07 5.07,5.07, height 0.61
ICC_UFQFPN28_4X4_P050 [mm] "MCD-02218"
  rect 0.3x0.3 smd mask+0.05: 1(-1.5,-2) 7(1.5,-2) 8(2,-1.5) 14(2,1.5) 15(1.5,2) 21(-1.5,2) 22(-2,1.5) 28(-2,-1.5)
  rect 0.3x0.55 smd mask+0.05: 2(-1,-1.875) 3(-0.5,-1.875) 4(0,-1.875) 5(0.5,-1.875) 6(1,-1.875) 16(1,1.875) 17(0.5,1.875) 18(0,1.875) 19(-0.5,1.875) 20(-1,1.875)
  rect 0.55x0.3 smd mask+0.05: 9(1.875,-1) 10(1.875,-0.5) 11(1.875,0) 12(1.875,0.5) 13(1.875,1) 23(-1.875,1) 24(-1.875,0.5) 25(-1.875,0) 26(-1.875,-0.5) 27(-1.875,-1)
  Top Layer region: -1.35,2.15 -1.35,1.65 -1.5,1.65 -1.65,1.8 -1.65,2.15
  Top Layer region: -2.15,1.35 -1.65,1.35 -1.65,1.5 -1.8,1.65 -2.15,1.65
  Top Layer region: -2.15,-1.35 -1.65,-1.35 -1.65,-1.5 -1.8,-1.65 -2.15,-1.65
  Top Layer region: -1.35,-2.15 -1.35,-1.65 -1.5,-1.65 -1.65,-1.8 -1.65,-2.15
  Top Layer region: 2.15,-1.35 1.65,-1.35 1.65,-1.5 1.8,-1.65 2.15,-1.65
  Top Layer region: 1.35,-2.15 1.35,-1.65 1.5,-1.65 1.65,-1.8 1.65,-2.15
  Top Layer region: 2.15,1.35 1.65,1.35 1.65,1.5 1.8,1.65 2.15,1.65
  Top Layer region: 1.35,2.15 1.35,1.65 1.5,1.65 1.65,1.8 1.65,2.15
  silkscreen extent -2,-2 2,2, body extent -2,-2 2,2, height 0.6
ICC_VFBGA49_3X3_P040 [mm] "MCD-02213"
  round 0.26 smd mask+0.03: A1(-1.2,1.2) A2(-0.8,1.2) A3(-0.4,1.2) A4(0,1.2) A5(0.4,1.2) A6(0.8,1.2) A7(1.2,1.2) B1(-1.2,0.8) B2(-0.8,0.8) B3(-0.4,0.8) B4(0,0.8) B5(0.4,0.8) B6(0.8,0.8) B7(1.2,0.8) C1(-1.2,0.4) C2(-0.8,0.4) C3(-0.4,0.4) C4(0,0.4) C5(0.4,0.4) C6(0.8,0.4) C7(1.2,0.4) D1(-1.2,0) D2(-0.8,0) D3(-0.4,0) D4(0,0) D5(0.4,0) D6(0.8,0) D7(1.2,0) E1(-1.2,-0.4) E2(-0.8,-0.4) E3(-0.4,-0.4) E4(0,-0.4) E5(0.4,-0.4) E6(0.8,-0.4) E7(1.2,-0.4) F1(-1.2,-0.8) F2(-0.8,-0.8) F3(-0.4,-0.8) F4(0,-0.8) F5(0.4,-0.8) F6(0.8,-0.8) F7(1.2,-0.8) G1(-1.2,-1.2) G2(-0.8,-1.2) G3(-0.4,-1.2) G4(0,-1.2) G5(0.4,-1.2) G6(0.8,-1.2) G7(1.2,-1.2)
  body extent -1.5,-1.5 1.5,1.5, height 1.01
ICC_VFBGA96_9x13_P080 [mm]
  round 0.4 smd mask+0.05: A1(-3.2,6) A2(-2.4,6) A3(-1.6,6) A7(1.6,6) A8(2.4,6) A9(3.2,6) B1(-3.2,5.2) B2(-2.4,5.2) B3(-1.6,5.2) B7(1.6,5.2) B8(2.4,5.2) B9(3.2,5.2) C1(-3.2,4.4) C2(-2.4,4.4) C3(-1.6,4.4) C7(1.6,4.4) C8(2.4,4.4) C9(3.2,4.4) D1(-3.2,3.6) D2(-2.4,3.6) D3(-1.6,3.6) D7(1.6,3.6) D8(2.4,3.6) D9(3.2,3.6) E1(-3.2,2.8) E2(-2.4,2.8) E3(-1.6,2.8) E7(1.6,2.8) E8(2.4,2.8) E9(3.2,2.8) F1(-3.2,2) F2(-2.4,2) F3(-1.6,2) F7(1.6,2) F8(2.4,2) F9(3.2,2) G1(-3.2,1.2) G2(-2.4,1.2) G3(-1.6,1.2) G7(1.6,1.2) G8(2.4,1.2) G9(3.2,1.2) H1(-3.2,0.4) H2(-2.4,0.4) H3(-1.6,0.4) H7(1.6,0.4) H8(2.4,0.4) H9(3.2,0.4) J1(-3.2,-0.4) J2(-2.4,-0.4) J3(-1.6,-0.4) J7(1.6,-0.4) J8(2.4,-0.4) J9(3.2,-0.4) K1(-3.2,-1.2) K2(-2.4,-1.2) K3(-1.6,-1.2) K7(1.6,-1.2) K8(2.4,-1.2) K9(3.2,-1.2) L1(-3.2,-2) L2(-2.4,-2) L3(-1.6,-2) L7(1.6,-2) L8(2.4,-2) L9(3.2,-2) M1(-3.2,-2.8) M2(-2.4,-2.8) M3(-1.6,-2.8) M7(1.6,-2.8) M8(2.4,-2.8) M9(3.2,-2.8) N1(-3.2,-3.6) N2(-2.4,-3.6) N3(-1.6,-3.6) N7(1.6,-3.6) N8(2.4,-3.6) N9(3.2,-3.6) P1(-3.2,-4.4) P2(-2.4,-4.4) P3(-1.6,-4.4) P7(1.6,-4.4) P8(2.4,-4.4) P9(3.2,-4.4) R1(-3.2,-5.2) R2(-2.4,-5.2) R3(-1.6,-5.2) R7(1.6,-5.2) R8(2.4,-5.2) R9(3.2,-5.2) T1(-3.2,-6) T2(-2.4,-6) T3(-1.6,-6) T7(1.6,-6) T8(2.4,-6) T9(3.2,-6)
  silkscreen extent -4.72,-6.55 4.55,6.73, body extent -4.55,-6.55 4.55,6.55, height 1
ICC_VFDFPN8-EPAD_3X3_P065 [mm] "MCD-02243"
  rect 0.35x0.55 smd mask+0.05: 1(-0.975,-1.475) 2(-0.325,-1.475) 3(0.325,-1.475) 4(0.975,-1.475) 5(0.975,1.475) 6(0.325,1.475) 7(-0.325,1.475) 8(-0.975,1.475)
  rect 2.55x1.65 smd mask+0.05: 9(0,0)
  Top Layer region: -0.8,-1.2 -0.813,-1.133 -0.851,-1.076 -0.908,-1.038 -0.975,-1.025 -0.975,-1.025 -1.042,-1.038 -1.099,-1.076 -1.137,-1.133 -1.15,-1.2 -1.15,-1.2
  Top Layer region: -0.15,-1.2 -0.163,-1.133 -0.201,-1.076 -0.258,-1.038 -0.325,-1.025 -0.325,-1.025 -0.392,-1.038 -0.449,-1.076 -0.487,-1.133 -0.5,-1.2 -0.5,-1.2
  Top Layer region: 0.5,-1.2 0.487,-1.133 0.449,-1.076 0.392,-1.038 0.325,-1.025 0.325,-1.025 0.258,-1.038 0.201,-1.076 0.163,-1.133 0.15,-1.2 0.15,-1.2
  Top Layer region: 1.15,-1.2 1.137,-1.133 1.099,-1.076 1.042,-1.038 0.975,-1.025 0.975,-1.025 0.908,-1.038 0.851,-1.076 0.813,-1.133 0.8,-1.2 0.8,-1.2
  Top Layer region: 0.8,1.2 0.813,1.133 0.851,1.076 0.908,1.038 0.975,1.025 0.975,1.025 1.042,1.038 1.099,1.076 1.137,1.133 1.15,1.2 1.15,1.2
  Top Layer region: 0.15,1.2 0.163,1.133 0.201,1.076 0.258,1.038 0.325,1.025 0.325,1.025 0.392,1.038 0.449,1.076 0.487,1.133 0.5,1.2 0.5,1.2
  Top Layer region: -0.5,1.2 -0.487,1.133 -0.449,1.076 -0.392,1.038 -0.325,1.025 -0.325,1.025 -0.258,1.038 -0.201,1.076 -0.163,1.133 -0.15,1.2 -0.15,1.2
  Top Layer region: -1.15,1.2 -1.137,1.133 -1.099,1.076 -1.042,1.038 -0.975,1.025 -0.975,1.025 -0.908,1.038 -0.851,1.076 -0.813,1.133 -0.8,1.2 -0.8,1.2
  silkscreen extent -1.5,-1.5 1.5,1.5, body extent -1.5,-1.5 1.5,1.5, height 1
ICC_VQFN24-EPAD_4X4_P050 [mm]
  rrect50% 0.85x0.3 smd mask+0.05: 1(-1.95,1.25) 2(-1.95,0.75) 3(-1.95,0.25) 4(-1.95,-0.25) 5(-1.95,-0.75) 6(-1.95,-1.25) 13(1.95,-1.25) 14(1.95,-0.75) 15(1.95,-0.25) 16(1.95,0.25) 17(1.95,0.75) 18(1.95,1.25)
  rrect50% 0.3x0.85 smd mask+0.05: 7(-1.25,-1.95) 8(-0.75,-1.95) 9(-0.25,-1.95) 10(0.25,-1.95) 11(0.75,-1.95) 12(1.25,-1.95) 19(1.25,1.95) 20(0.75,1.95) 21(0.25,1.95) 22(-0.25,1.95) 23(-0.75,1.95) 24(-1.25,1.95)
  rect 2.6x2.6 smd paste-10 mask+0.05: EP(0,0)
  body extent -2.05,-2.05 2.05,2.05, height 1.1
ICC_VSSOP8_DCU_R-PDSO-G8_2X2P30_P050 [mm]
  rect 0.3x0.8 smd mask+0.05: 1(-0.75,-1.55) 2(-0.25,-1.55) 3(0.25,-1.55) 4(0.75,-1.55) 5(0.75,1.55) 6(0.25,1.55) 7(-0.25,1.55) 8(-0.75,1.55)
  silkscreen extent -1.05,-1.2 1.05,1.2, body extent -1.05,-1.62 1.05,1.62, height 0.9
ICC_WFQFN44-EPAD_5X6_P040 [mm]
  rect 0.8x0.2 smd mask+0.05: 1(-2.45,2.2) 2(-2.45,1.8) 3(-2.45,1.4) 4(-2.45,1) 5(-2.45,0.6) 6(-2.45,0.2) 7(-2.45,-0.2) 8(-2.45,-0.6) 9(-2.45,-1) 10(-2.45,-1.4) 11(-2.45,-1.8) 12(-2.45,-2.2) 23(2.45,-2.2) 24(2.45,-1.8) 25(2.45,-1.4) 26(2.45,-1) 27(2.45,-0.6) 28(2.45,-0.2) 29(2.45,0.2) 30(2.45,0.6) 31(2.45,1) 32(2.45,1.4) 33(2.45,1.8) 34(2.45,2.2)
  rect 0.2x0.8 smd mask+0.05: 13(-1.8,-2.95) 14(-1.4,-2.95) 15(-1,-2.95) 16(-0.6,-2.95) 17(-0.2,-2.95) 18(0.2,-2.95) 19(0.6,-2.95) 20(1,-2.95) 21(1.4,-2.95) 22(1.8,-2.95) 35(1.8,2.95) 36(1.4,2.95) 37(1,2.95) 38(0.6,2.95) 39(0.2,2.95) 40(-0.2,2.95) 41(-0.6,2.95) 42(-1,2.95) 43(-1.4,2.95) 44(-1.8,2.95)
  rect 3.6x4.6 smd paste-1.8 mask+0.05: ep(0,0)
  body extent -2.5,-3 2.5,3, height 0.81
IND_0402_MURATA_LQW15AN2N4C00X [mm]
  rect 0.65x0.9 smd mask+0.05: 1(-0.475,0) 2(0.475,0)
  silkscreen extent -0.05,-0.35 0.05,0.35, body extent -0.55,-0.35 0.55,0.35, height 0.6
IND_2520_TOKO_DFE252012P [mm]
  rect 0.8x2 smd mask+0.05: 1(-1,0) 2(1,0)
  silkscreen extent -1.35,-1.12 1.35,1.12, body extent -1.35,-1.1 1.35,1.1, height 2
IND_4025_WURTH_74404043022A [mm] "MCD-02242"
  rect 1.5x4.4 smd mask+0.05: 1(-1.525,0) 2(1.525,0)
  silkscreen extent -1.84,-2.1 1.84,2.1, body extent -2.1,-2.1 2.1,2.1, height 2.5
L0603 [mm]
  rect 0.8x0.95 smd mask+0.05: 1(-0.8,0) 2(0.8,0)
  Top Layer keep-out region: -0.4,-0.475 0.4,-0.475 0.4,0.475 -0.4,0.475
  body extent -0.87,-0.47 0.87,0.47, height 0.95
L1210_LQH [mm]
  rect 1.7x3.1 smd mask+0.05: 1(-1.1,0) 2(1.1,0)
  silkscreen extent -2.05,-1.65 2.05,1.65, body extent -1.75,-1.35 1.75,1.35, height 2
LCD_DRAWING_ROCKTEK_RK043FN78H-CT661C [mm] "MCD-02422"
  silkscreen extent -52.62,-45 52.88,22.2, body extent -52.62,-45 52.88,22.2, height 4.53
LED_0603_GREEN [mm]
  rect 0.8x0.8 smd mask+0.05: 1(-0.75,0) 2(0.75,0)
  Top Layer keep-out region: -0.35,0.4 0.35,0.4 0.35,-0.4 -0.35,-0.4
  body extent -0.8,-0.4 0.8,0.4, height 0.6
LED_0603_ORANGE_H0P4 [mm]
  rect 0.8x0.8 smd mask+0.05: 1(-0.75,0) 2(0.75,0)
  Top Layer keep-out region: -0.35,0.4 0.35,0.4 0.35,-0.4 -0.35,-0.4
  body extent -0.8,-0.4 0.79,0.4, height 0.4
LED_0603_RED [mm]
  rect 0.8x0.8 smd mask+0.05: 1(-0.75,0) 2(0.75,0)
  Top Layer keep-out region: -0.35,0.4 0.35,0.4 0.35,-0.4 -0.35,-0.4
  body extent -0.8,-0.4 0.8,0.4, height 0.6
LED_0603_SMD-B_BLUE_H0P4 [mm]
  rect 0.6x1 smd mask+0.05: 1(-0.65,0) 2(0.65,0)
  Top Layer keep-out region: -0.35,0.5 0.35,0.5 0.35,-0.5 -0.35,-0.5
  body extent -0.85,-0.45 0.85,0.45, height 0.5
LED_BI-GR_CMD67-22 [mm] "MCD-02629"
  rect 1.1x1.5 smd mask+0.05: 1(-0.75,-1.5) 2(0.75,-1.5) 3(-0.75,1.5) 4(0.75,1.5)
  silkscreen extent -1.5,-1.7 1.7,1.9, body extent -1.5,-1.85 1.5,1.85, height 2.1
MIRE_PLACE_SMD_0P8MM [mm]
  round 0.8 smd paste-10 mask+0.2: 1(0,0)
  Top Layer keep-out circle w0.01: c0,0 r0.804
MOD_WLAN-BT_MURATA_LBEE5KL1DX-883 [mm]
  rect 0.25x0.5 smd mask+0.05: 1(-2.25,-2.025) 2(-1.8,-2.025) 3(-1.35,-2.025) 4(-0.9,-2.025) 5(-0.45,-2.025) 6(0,-2.025) 7(0.45,-2.025) 8(0.9,-2.025) 9(1.35,-2.025) 10(1.8,-2.025) 11(2.25,-2.025) 22(2.25,2.025) 23(1.8,2.025) 24(1.35,2.025) 25(0.9,2.025) 26(0.45,2.025) 27(0,2.025) 28(-0.45,2.025) 29(-0.9,2.025) 30(-1.35,2.025) 31(-1.8,2.025) 32(-2.25,2.025)
  rect 0.5x0.375 smd mask+0.05: 12(2.925,-2.087) 21(2.925,2.087) 33(-2.925,2.087) 42(-2.925,-2.087)
  rect 0.5x0.25 smd mask+0.05: 13(2.925,-1.575) 14(2.925,-1.125) 15(2.925,-0.675) 16(2.925,-0.225) 17(2.925,0.225) 18(2.925,0.675) 19(2.925,1.125) 20(2.925,1.575) 34(-2.925,1.575) 35(-2.925,1.125) 36(-2.925,0.675) 37(-2.925,0.225) 38(-2.925,-0.225) 39(-2.925,-0.675) 40(-2.925,-1.125) 41(-2.925,-1.575)
  rect 1x1 smd mask+0.05: 43(-1,-0.75) 44(1,-0.75) 45(-1,0.75) 46(1,0.75)
  silkscreen extent -3.57,-2.68 3.57,2.68, body extent -3.57,-2.68 3.57,2.68, height 1.11
MOS_POWERFLAT_3P3X3P3_P065 [mm] "MCD-01126"
  rect 0.4x0.75 smd mask+0.05: 1(-0.975,-1.525) 2(-0.325,-1.525) 3(0.325,-1.525) 4(0.975,-1.525) 6(0.325,1.525) 7(-0.325,1.525)
  rect 0.45x0.75 smd mask+0.05: 5(1,1.525) 8(-1,1.525)
  Top Layer region: -1.755,0.2 -1.755,-0.2 -1.225,-0.2 -1.225,-0.5 1.225,-0.5 1.225,-0.2 1.755,-0.2 1.755,0.2 1.225,0.2 1.225,1.9 -1.225,1.9 -1.225,0.2
  body extent -1.75,-1.75 1.75,1.75, height 0.91
MOS_SOT23 [mm]
  rect 1x1.4 smd mask+0.05: 1(-0.95,-1.1) 2(0.95,-1.1) 3(0,1.1)
  silkscreen extent -1.63,-0.82 1.63,0.82, body extent -1.56,-1.25 1.56,1.25, height 1.1
OSC_NDK_NZ2520SB_4P [mm]
  rect 1x1 smd mask+0.05: 1(-0.825,-0.625) 2(0.825,-0.625) 3(0.825,0.625) 4(-0.825,0.625)
  silkscreen extent -1.43,-1.22 1.2,1.05, body extent -1.3,-1.05 1.3,1.05, height 0.91
PowerFLAT_5x6 [mm] "MCD-02152"
  rect 0.65x1.25 smd mask+0.05: 1(1.905,2.675) 2(0.635,2.675) 3(-0.635,2.675) 4(-1.905,2.675) 5(-1.905,-2.675) 6(-0.635,-2.675) 7(0.635,-2.675) 8(1.905,-2.675)
  Top Layer region: -0.2,-3.3 -0.95,-3.3 -0.95,-2.75 -1.575,-2.75 -1.575,-3.3 -2.3,-3.3 -2.3,-2.3 -2.7,-2.3 -2.7,-1.5 -2.3,-1.5 -2.3,0.15 -2.7,0.15 -2.7,0.975 -2.3,0.975 -2.3,1.15 -0.2,1.15
  Top Layer region: 0.2,-3.3 0.95,-3.3 0.95,-2.75 1.575,-2.75 1.575,-3.3 2.3,-3.3 2.3,-2.3 2.7,-2.3 2.7,-1.5 2.3,-1.5 2.3,0.15 2.7,0.15 2.7,0.975 2.3,0.975 2.3,1.15 0.2,1.15
  silkscreen extent -2.5,-3 2.5,3, body extent -2.6,-3.08 2.6,3.07, height 1
R0402#1 [mm]
  rect 0.51x0.7 smd mask+0.05: 1(-0.45,0) 2(0.45,0)
  Top Layer keep-out region: -0.175,-0.35 0.175,-0.35 0.175,0.35 -0.175,0.35
  body extent -0.52,-0.3 0.52,0.3, height 0.4
R0402#2 [mm]
  rect 0.51x0.7 smd mask+0.05: 1(-0.45,0) 2(0.45,0)
  body extent -0.52,-0.3 0.52,0.3, height 0.4
R0603 [mm]
  rect 0.64x1 smd mask+0.05: 1(-0.7,0) 2(0.7,0)
  Top Layer keep-out region: -0.375,-0.5 0.375,-0.5 0.375,0.5 -0.375,0.5
  body extent -0.9,-0.5 0.9,0.5, height 0.56
REG_SOT23-5L [mm]
  rect 0.6x1.3 smd mask+0.05: 1(-0.95,-1.1) 2(0,-1.1) 3(0.95,-1.1) 4(0.95,1.1) 5(-0.95,1.1)
  silkscreen extent -1.6,-0.95 1.6,0.97, body extent -1.52,-1.25 1.52,1.25, height 1.1
Sheetbox_6L2S [mil] "Sheetbox 6 layers / 2 silkscreens"
  round 20 on Mech16: 1(813.5,208.05) 1(2736.63,208.05)
STICKER_BOARD_25X9 [mm] "Sticker to mention board CPN code"
  silkscreen extent -12.5,-4.5 12.5,4.5
STICKER_PRODUCT_25X9 [mm] "Sticker to mention board CPN code"
  silkscreen extent -12.5,-4.5 12.5,4.5
SWI_GRAYHILL-INC_76SB04ST [mm] "MCD-02256"
  rect 1.5x1.5 hole 0.9 mask+0.05: 1(-3.75,-3.81)
  round 1.5 hole 0.9 mask+0.05: 2(-1.25,-3.81) 3(1.25,-3.81) 4(3.75,-3.81) 5(3.75,3.81) 6(1.25,3.81) 7(-1.25,3.81) 8(-3.75,3.81)
  silkscreen extent -6.1,-4.82 6.1,4.82, body extent -6.1,-4.83 6.1,4.82, height 6.9
SWI_KNITTER_TSS644S [mm] "MCD-02417"
  rect 1.55x1.3 smd mask+0.05: 1(-3.975,2.25) 2(3.975,2.25) 3(-3.975,-2.25) 4(3.975,-2.25)
  silkscreen extent -3.1,-3.1 3.1,3.1, body extent -4.5,-3.1 4.5,3.1, height 7.3
TP_SMD_1MM [mm]
  round 1 smd paste-10 mask+0.05: 1(0,0)
  silkscreen extent -0.7,-0.7 0.7,0.7
TP_SMD_2MM [mm]
  round 2 smd paste-10 mask+0.05: 1(0,0)
  silkscreen extent -1.2,-1.2 1.2,1.2

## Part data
B1 B2 B3 B4 B5: library part MCD-02417, "Push Button, NO, 0.05A, 12V, 2.6N, SMD, 9.0x6.2mm, T=7.3mm, changeable caps KTSC-6xx", Manufacturer=KNITTER-SWITCH, Manufacturer_Part_Number=TSS644S, Package=9.0x6.2mm
C1 C2 C3 C4: library part MCD-00200, "Capacitor, MLCC, 12pF, 50V, NPO, +/-5%, 0402, T=0.5mm", Manufacturer=YAGEO, Manufacturer_Part_Number=CC0402JRNPO9BN120, Package=0402
C5 C10 C17 C23 C24 C40 C92 C171 C173 C174 C176 C177 C182 C183 C185 C186 C187 C188 C189 C190 C191 C194 C195 C196 C197 C198 C199 C200 C201 C202 C203 C205 C207 C208 C209 C212 C213 C214 C215 C219: library part MCD-02377, "Capacitor, MLCC, 1uF, 6.3V, X5R, +/-20%, 0201, T=0,3mm", Manufacturer=MURATA, Manufacturer_Part_Number=GRM033R60J105MEA2, Package=0201
C6 C36 C43 C122 C141 C143 C146 C160: library part MCD-00095, "Capacitor, MLCC, 1uF, 25V, X5R, +/-10%, 0402, T=0.5mm", Manufacturer=MURATA, Manufacturer_Part_Number=GRM155R61E105KA12, Package=0402
C7 C8 C9 C11 C12 C13 C15 C16 C22 C25 C26 C28 C30 C31 C32 C33 C35 C37 C41 C44 C46 C47 C48 C49 C53 C57 C58 C59 C61 C62 C63 C65 C67 C68 C69 C70 C71 C74 C75 C76 C77 C78 C79 C80 C81 C82 C83 C85 C89 C94 C102 C104 C105 C106 C107 C108 C118 C119 C121 C135 C138 C150 C152 C153 C154 C157 C158 C163 C165 C169 C170 C178 C179 C180 C181 C210 C218 C220 C226 C227: library part MCD-00006, "Capacitor, MLCC, 100nF, 16V, X7R, +/-10%, 0402, T=0.5mm", Manufacturer=YAGEO, Manufacturer_Part_Number=CC0402KRX7R7BB104, Package=0402
C14 C34 C54 C55 C117 C140 C223 C228: library part MCD-02198, "Capacitor, MLCC, 10nF, 50V, X7R, +/-10%, 0402, T=0.5mm", Manufacturer=YAGEO, Manufacturer_Part_Number=CC0402KRX7R9BB103, Package=0402
C18 C60 C64 C73 C216 C217: library part MCD-02235, "Capacitor, MLCC, 2.2uF, 10V, X5R,+/-10%, 0201, T=0.5mm", Manufacturer=MURATA, Manufacturer_Part_Number=GRM033R61A225KE47D, Package=0201
C19 C27 C29 C39 C91 C112 C120 C123 C125 C131 C134 C172: library part MCD-00099, "Capacitor, MLCC, 10uF, 10V, X5R, +/-10%, 0603, T=0.8mm", Manufacturer=MURATA, Manufacturer_Part_Number=GRM188R61A106KE69D, Package=0603
C20 C21 C42 C50 C99 C100 C101 C109 C132 C139 C142 C144 C145 C168: library part MCD-01356, "Capacitor, MLCC, 4.7uF, 6V3, X5R, +/-20%, 0402, T=0.5mm", Manufacturer=MURATA, Manufacturer_Part_Number=GRM155R60J475ME47, Package=0402
C38 C90 C147 C148 C151 C156: library part MCD-00724, "Capacitor, MLCC, 470pF, 50V, NPO, +/-5%, 0402, T=0.5mm", Manufacturer=YAGEO, Manufacturer_Part_Number=CC0402JRNPO9BN471, Package=0402
C45 C51: library part MCD-00013, "Capacitor, MLCC, 4.7uF, 50V, X7R, +/-10%, 1206, T=1.27mm", Manufacturer=AVX, Manufacturer_Part_Number=12065C475KAT2A, Package=1206
C52 C149 C155: library part MCD-01099, "Capacitor, MLCC, 100nF, 50V, X7R, +/-10%, 0603, T=0.8mm", Manufacturer=YAGEO, Manufacturer_Part_Number=CC0603KRX7R9BB104, Package=0603
C56: library part MCD-00277, "Capacitor, MLCC, 33pF, 50V, NPO,+/-5%, 0402, T=0.5mm", Manufacturer=YAGEO, Manufacturer_Part_Number=CC0402JRNPO9BN330, Package=0402
C66 C72 C110 C111 C113 C114 C115 C116 C124 C126 C127 C128 C129 C133: library part MCD-00100, "Capacitor, MLCC, 22uF, 6V3, X5R, +/-20%, 0603, T=0.8mm", Manufacturer=MURATA, Manufacturer_Part_Number=GRM188R60J226MEA0J, Package=0603
C84 C161 C221 C229: library part MCD-00205, "Capacitor, MLCC, 100pF, 50V, NPO, +/-5%, 0402, T=0.5mm", Manufacturer=YAGEO, Manufacturer_Part_Number=CC0402JRNPO9BN101, Package=0402
C86: library part MCD-00198, "Capacitor, MLCC, 1nF, 16V, X7R, +/-10%, 0402, T=0.5mm", Manufacturer=TDK, Manufacturer_Part_Number=C1005NP01H220J050BA, Package=0402
C87: library part MCD-01995, "Capacitor, MLCC, 22pF, 50V, C0G, +/-5%, 0402, T=0.5mm", Manufacturer=TDK, Manufacturer_Part_Number=C1005NP01H220J050BA, Package=0402
C88 C93 C95 C96 C98 C103 C159 C164: library part MCD-00674, "Capacitor, MLCC, 6.8pF, 50V, NPO, +/-0.25pF, 0402, T=0.5mm", Manufacturer=YAGEO, Manufacturer_Part_Number=CC0402CRNPO9BN6R8, Package=0402
C130: library part MCD-02263, "Capacitor, MLCC, 47uF, 25V, X5R, 20%, 1206, T=1.6mm", Manufacturer=MURATA, Manufacturer_Part_Number=GRM31CR61E476ME44, Package=C1206
C136 C137 C162 C224 C225: library part MCD-00104, "Capacitor, MLCC, 220uF, 6V3, X5R, +/-20%, 1206, T=1.6mm", Manufacturer=MURATA, Manufacturer_Part_Number=GRM31CR60J227ME11, Package=1206
C166: library part MCD-02196, "Capacitor, MLCC, 4.7uF, 25V, X5R, +/-10%, 0603, T=0.8mm", Manufacturer=TDK, Manufacturer_Part_Number=C1608X5R1E475K080AC, Package=0603
C167: library part MCD-02457, "Capacitor, MLCC, 2.2nF, 50V, C0G/NPO, +/-5%, 0603, T=0,8mm", Manufacturer=YAGEO, Manufacturer_Part_Number=CC0603JRNPO9BN222, Package=0603
C175 C184 C192 C193 C204 C206 C211: library part MCD-01729, "Capacitor, MLCC, 1nF, 25V, X7R,+/-5%, 0201,T=0.3mm", Manufacturer=MURATA, Manufacturer_Part_Number=GRM033R71E102JA01D, Package=0201
C222: library part MCD-02378, "Capacitor, MLCC, 10uF, 50V, X7R, +/-10%, 1210, T=2.5mm", Manufacturer=TDK, Manufacturer_Part_Number=C3225X7R1H106K250AC, Package=1210
CN1: library part MCD-02225, "Socket_FFC/FPC, 15pins, 1mm ,VR, SMD, T=7.7mm", Manufacturer="TE CONNECTIVITY", Manufacturer_Part_Number=1-1734248-5
CN3: library part MCD-00653, "Connector_uSD Card, Top Mnt Push-Push", Manufacturer=ATOM
CN4 CN15: library part MCD-02475, "connector_RJ45, 10/100 Ethernet integrated MAG with integrate Green and Yellow LED, T= 13.61mm", Manufacturer=PENGHUI, Manufacturer_Part_Number=RMT-119A-12F6-GY-02
CN5 CN6: library part MCD-00109, "USB_Dual-TypeA, Receptacle, 8pins, 2.5mm, RA, TH, T= 15.5mm", Manufacturer=CONEXCON, Manufacturer_Part_Number=5600-3081
CN7 CN12: library part MCD-02421, "USB_TypeC, 24 pins, RA, SMD, T=3.71mm (USB Certified 3.1)", Manufacturer=MOLEX, Manufacturer_Part_Number=2012670005
CN8: library part MCD-00302, "Header, 20x2, 2.54mm, VR, TH, T=5.84mm/2.54mm", Manufacturer=SAMTEC, Manufacturer_Part_Number=TSW-120-07-G-D
CN9 CN13: library part MCD-00029, "Header, 4x1, 2.54mm, VR, TH, T=5.84mm/2.54mm", Manufacturer=SAMTEC, Manufacturer_Part_Number=TSW-104-07-G-S
CN10: library part MCD-00028, "MicroUSB_TypeB, 5pins, 0.65mm, RA, SMD, T=2.9mm", Manufacturer=MOLEX, Manufacturer_Part_Number=1050170001
CN11: library part MCD-00655, "Header, 2x1, 1.25mm, VR, TH, T=2.25mm/2.3mm", Manufacturer=MOLEX, Manufacturer_Part_Number=53047-0210
CN14: library part MCD-02123, "Header, 7x2, 2.54mm, VR, TH, T=5.84mm/2.54mm", Manufacturer=SAMTEC, Manufacturer_Part_Number=TSW-107-07-G-D
CN16: library part MCD-02589, "Socket_FFC/FPC, 40pins, 0.5mm, RA, SMD, T=1.9mm", Manufacturer=MOLEX
D1 D3 D4: library part MCD-00034, Manufacturer=STMICROELECTRONICS, Manufacturer_HQ_COO=EU
D2: library part MCD-00033, "Low Drop power Schottky rectifier(1A, 40V, 0.4V)", Manufacturer=STMICROELECTRONICS, Manufacturer_HQ_COO=EU
D5: library part MCD-01677, "Small signal Schottky diodes", Manufacturer=STMICROELECTRONICS, Manufacturer_HQ_COO=EU, Manufacturer_Part_Number=BAT54KFILM, Package=SOD-523
HW2: library part MCD-00235, "Sticker Board 25x9 mm", Manufacturer=N/A
HW3: library part MCD-00547, "Sticker product 25x9 mm", Manufacturer=N/A
L1: library part MCD-00657, "Inductor, 2.4nH, +/-0.2nH, Itemp=850mA, 50R, 0402, T=0.6mm, Qmin=20", Manufacturer=MURATA, Manufacturer_Part_Number=LQW15AN2N4C00#, Package=0402
L2: library part MCD-00659, "Inductor, 2.2uH, +/-20%, 1050mA, 0R2, 0603, T=1mm", Manufacturer=MURATA, Manufacturer_Part_Number=LQM18PN2R2MGH, Package=0603
L3: library part MCD-00048, "Inductor, 4.7uH, +/-30%, 1A, 180mR, 1210, T=1.7mm", Manufacturer=MURATA, Manufacturer_Part_Number=LQH32PN4R7NN0L, Package=1210
L4 L5: library part MCD-00047, "Ferrite bead, 600R @1 00MHz, +/-25%, 350mA, 0R5, 0603, T=0.8mm", Manufacturer=TAI-TECH, Manufacturer_Part_Number=FCM1608KF-601T03, Package=0603
L6 L7 L9 L11: library part MCD-01122, "Inductor, 1uH, +/-20%, 4.3A max, 0R042, 2520, T=1.2mm", Manufacturer=MURATA, Manufacturer_Part_Number=DFE252012P-1ROM{}P2, Package=2520
L8: library part MCD-02242, "Inductor, 2.2uH, +/-30%, 3,83A, 0R023, 4x4mm, T=2.5mm", Manufacturer="WURTH ELEKTRONIK", Manufacturer_Part_Number=74404043022A, Package=4x4mm
L12: library part MCD-00305, "Ferrite bead, 26R @ 100Mhz, +/-25%, 6000mA, 0R007, 0603, T=0.75mm", Manufacturer=MURATA, Manufacturer_Part_Number=BLM18KG260TN1, Package=0603
LD1 LD7: library part MCD-00050, "LED, Green, 0603", Manufacturer=EVERLIGHT, Manufacturer_Part_Number=19-213SYGC/S530-E2/TR8, Package="LED 0603"
LD2 LD4: library part MCD-00049, "LED, Red, 0603", Manufacturer=EVERLIGHT, Manufacturer_Part_Number=19-213-R6C-AP1Q2B/3T, Package="LED 0603"
LD3: library part MCD-01131, "LED Blue, 0603 SMD, Forward Voltage Min=2,8V, Max=3,1V", Manufacturer=EVERLIGHT, Manufacturer_Part_Number=19-217-BHC-ZL1M2RY-3T, Package=0603
LD5: library part MCD-02629, "LED Bicolor, Green, Red, 4-PLCC", Manufacturer="VISUAL COMMUNICATIONS COMPANY - VCC", Manufacturer_Part_Number=CMD6722VRVGCTR8, Package=4-PLCC
LD6: library part MCD-00321, "LED, Orange, 0603", Manufacturer=EVERLIGHT, Manufacturer_Part_Number=19-217/S2C-AM2N2VY/3T, Package="LED 0603"
Q1 Q2: library part MCD-02152, "MOSFET, Dual N-channel 30 V, 0.016 Ω typ., 40 A, STripFET™ H5 Power MOSFET", Manufacturer=STMICROELECTRONICS, Manufacturer_HQ_COO=EU, Package="PowerFLAT 5x6"
Q3: library part MCD-01810, "N-channel 30 V, 6 mΩ typ, 11 A STripFET™ H6, Power MOSFET in a PowerFLAT™ 3.3x3.3 package", Manufacturer=STMICROELECTRONICS, Manufacturer_HQ_COO=EU, Package="PowerFLAT 3.3x3.3"
R1 R2 R10 R11 R12 R19 R20 R21 R28 R30 R45 R54 R55 R56 R57 R60 R61 R64 R68 R77 R81 R85 R88 R90 R91 R96 R103 R104 R105 R106 R114 R115 R133 R140 R166 R167 R188 R189 R190 R191 R192: library part MCD-00052, "Resistor, 0R, 0402, +/-5%, 1/16W", Manufacturer=YAGEO, Manufacturer_Part_Number=RC0402JR-070RL, Package=0402
R3 R4 R5 R6 R7 R8 R9 R22 R23 R24 R25 R26 R29 R32 R33 R34 R38 R43 R48 R65 R69 R70 R72 R73 R78 R83 R84 R93 R100 R102 R141 R150 R162 R163 R176 R178 R180 R187: library part MCD-00053, "Resistor, 10K, 0402, +/-1%, 1/16W", Manufacturer=YAGEO, Manufacturer_Part_Number=RC0402FR-0710KL, Package=0402
R13 R53 R58 R59 R87 R89 R94: library part MCD-00065, "Resistor, 4K7, 0402, +/-1%, 1/16W", Manufacturer=YAGEO, Manufacturer_Part_Number=RC0402FR-074K7L, Package=0402
R14 R15 R16 R17 R18 R144 R149: library part MCD-00063, "Resistor, 47K, 0402, +/-1%, 1/16W", Manufacturer=YAGEO, Manufacturer_Part_Number=RC0402FR-0747KL, Package=0402
R27 R52 R76 R110: library part MCD-00441, "Resistor, 270R, 0402, +/-1%, 1/16W", Manufacturer=YAGEO, Manufacturer_Part_Number=RC0402FR-07270RL, Package=0402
